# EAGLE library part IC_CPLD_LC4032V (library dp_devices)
32 Macrocells 3.3V CPLD
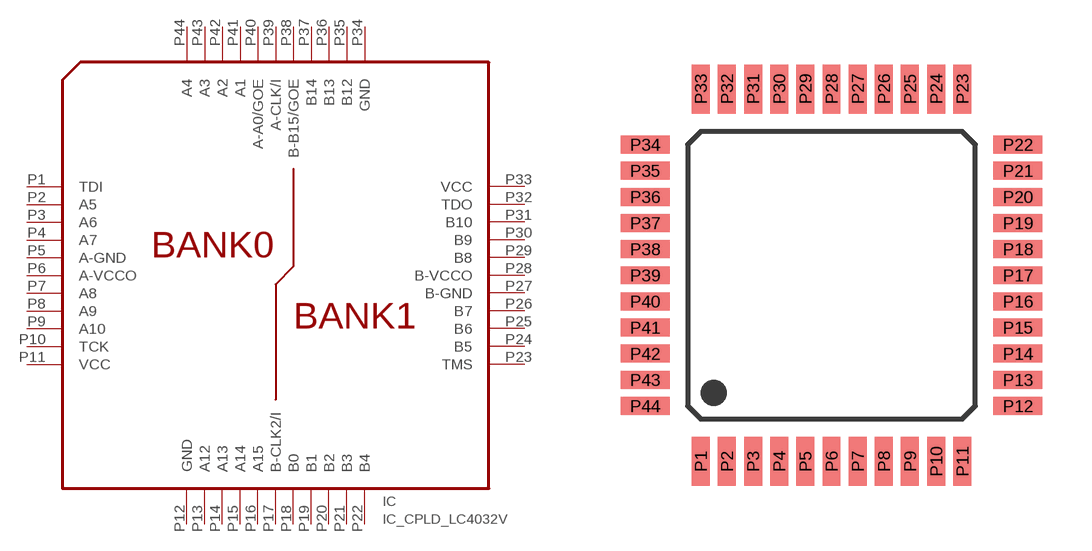
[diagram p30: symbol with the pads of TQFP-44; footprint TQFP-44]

Designator prefix IC

## IC_CPLD_LC4032V-TQFP44  [TQFP-44]
P1  TDI  in
P2  A5
P3  A6
P4  A7
P5  A-GND
P6  A-VCCO
P7  A8
P8  A9
P9  A10
P10  TCK  in
P11  VCC
P12  GND
P13  A12
P14  A13
P15  A14
P16  A15
P17  B-CLK2/I
P18  B0
P19  B1
P20  B2
P21  B3
P22  B4
P23  TMS  in
P24  B5
P25  B6
P26  B7
P27  B-GND
P28  B-VCCO
P29  B8
P30  B9
P31  B10
P32  TDO  out
P33  VCC
P34  GND
P35  B12
P36  B13
P37  B14
P38  B-B15/GOE
P39  A-CLK/I
P40  A-A0/GOE
P41  A1
P42  A2
P43  A3
P44  A4

## Footprint TQFP-44 (pad centres in mm)
smd 0.55 x 1.5: P1 -4,-5.7; P2 -3.2,-5.7; P3 -2.4,-5.7; P4 -1.6,-5.7; P5 -0.8,-5.7; P6 0,-5.7; P7 0.8,-5.7; P8 1.6,-5.7; P9 2.4,-5.7; P10 3.2,-5.7; P11 4,-5.7; P23 4,5.7; P24 3.2,5.7; P25 2.4,5.7; P26 1.6,5.7; P27 0.8,5.7; P28 0,5.7; P29 -0.8,5.7; P30 -1.6,5.7; P31 -2.4,5.7; P32 -3.2,5.7; P33 -4,5.7
smd 1.5 x 0.55: P12 5.7,-4; P13 5.7,-3.2; P14 5.7,-2.4; P15 5.7,-1.6; P16 5.7,-0.8; P17 5.7,0; P18 5.7,0.8; P19 5.7,1.6; P20 5.7,2.4; P21 5.7,3.2; P22 5.7,4; P34 -5.7,4; P35 -5.7,3.2; P36 -5.7,2.4; P37 -5.7,1.6; P38 -5.7,0.8; P39 -5.7,0; P40 -5.7,-0.8; P41 -5.7,-1.6; P42 -5.7,-2.4; P43 -5.7,-3.2; P44 -5.7,-4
